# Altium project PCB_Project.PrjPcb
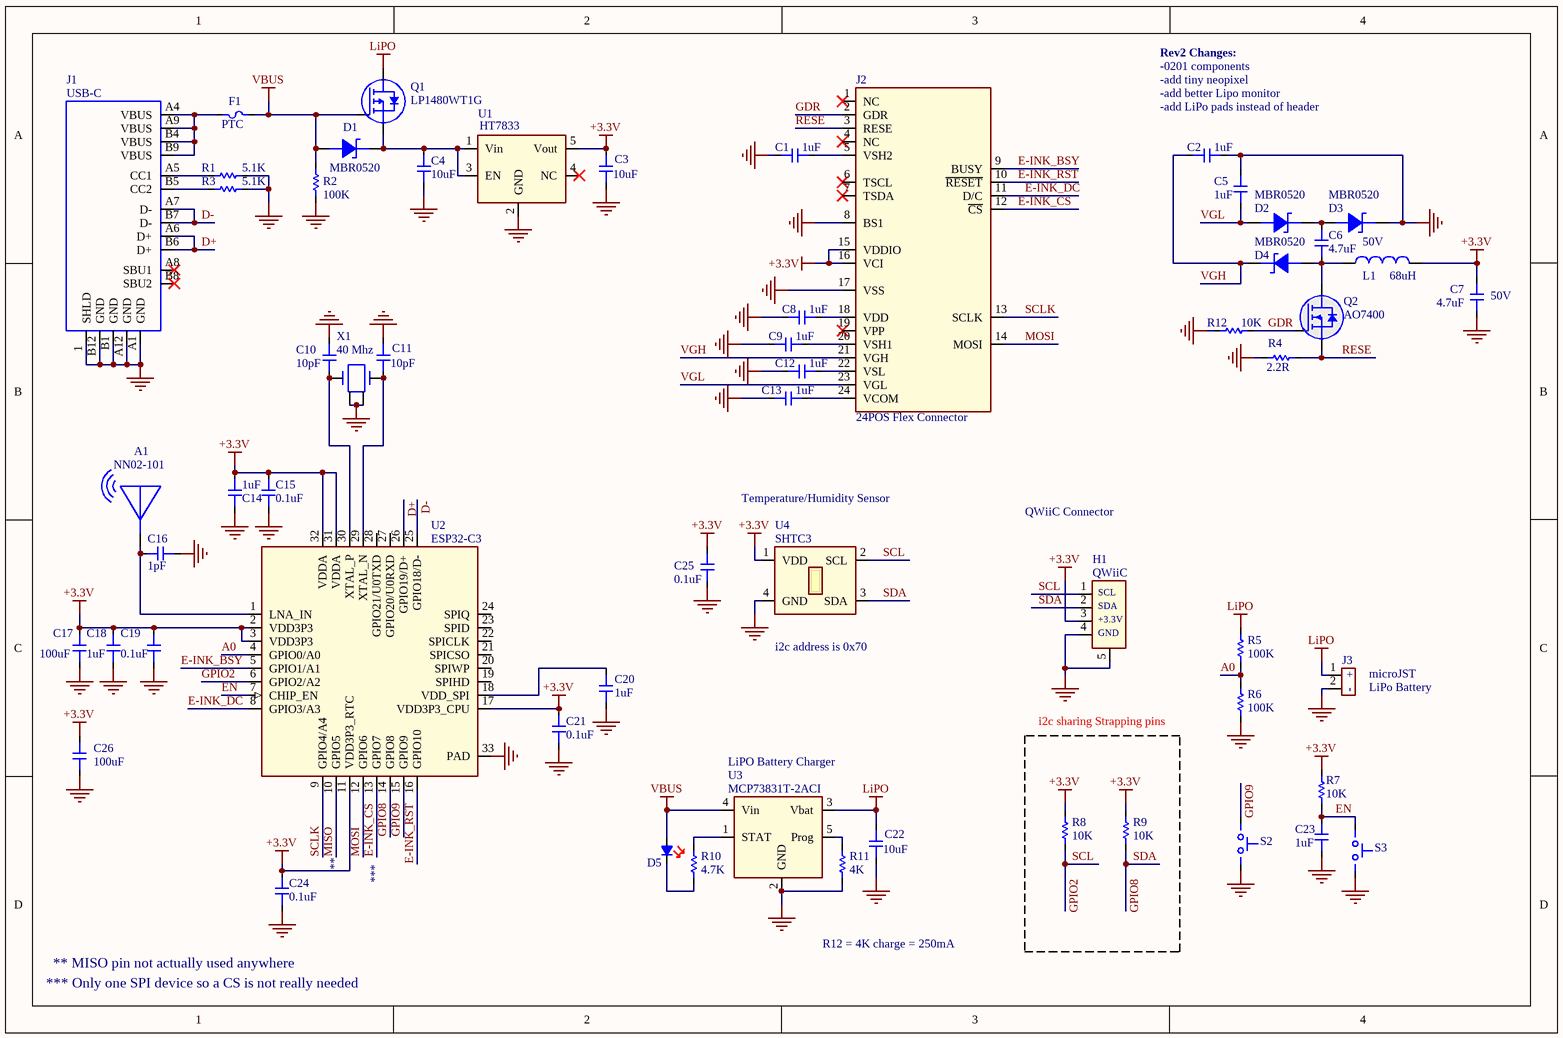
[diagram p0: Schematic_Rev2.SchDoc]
1 sheet, 59 parts. Net scope: global (net labels, ports and power ports of the same name join across sheets).
Board file: PCB_Rev2.PcbDoc

## Sheet Schematic_Rev2.SchDoc
size A4; SheetNumber: 1; SheetTotal: 1

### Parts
A1  NN02-101  [NN02-101]
C1  1uF  [CAPC0603X56N]
C2  1uF  [CAPC1005X56N]
C3  10uF  [CAPC2012X140N]
C4  10uF  [CAPC2012X140N]
C5  1uF  [CAPC1005X56N]
C6  4.7uF  [CAPC1608X09L]
C7  4.7uF  [CAPC1608X09L]
C8  1uF  [CAPC0603X56N]
C9  1uF  [CAPC0603X56N]
C10  10pF  [CAPC0603X56N]
C11  10pF  [CAPC0603X56N]
C12  1uF  [CAPC0603X56N]
C13  1uF  [CAPC0603X56N]
C14  1uF  [CAPC0603X56N]
C15  0.1uF  [CAPC0603X56N]
C16  1pF  [CAPC0603X56N]
C17  100uF  [CAPC3216X160N]
C18  1uF  [CAPC0603X56N]
C19  0.1uF  [CAPC0603X56N]
C20  1uF  [CAPC0603X56N]
C21  0.1uF  [CAPC0603X56N]
C22  10uF  [CAPC2012X140N]
C23  1uF  [CAPC0603X56N]
C24  0.1uF  [CAPC0603X56N]
C25  0.1uF  [CAPC0603X56N]
C26  100uF  [CAPC3216X160N]
D1  value MBR0520  [SOD123]  (hidden comment: MBR0520-TP)
D2  value MBR0520  [SOD123]  (hidden comment: MBR0520-TP)
D3  value MBR0520  [SOD123]  (hidden comment: MBR0520-TP)
D4  value MBR0520  [SOD123]  (hidden comment: MBR0520-TP)
D5  Red Led  [LED1005X40N-Red]  (value not drawn)
F1  PTC  [RESC1608X06L (0603 FOOTPRINT)]
H1  QWiiC  [SM04B-SRSS-TB]
J1  USB-C  [TYPE-C-31-M-12]
J2  24POS Flex Connector  [687124182122]
J3  CON2  [JST_Micro_2PIN]  (value not drawn)  (no BOM)
L1  68uH  [INDUCTOR, 3mmX3mm]
Q1  LP1480WT1G  [SC-70]
Q2  AO7400  [SC-70]
R1  5.1K  [RESC0603X40L (0201 footprint)]
R2  100K  [RESC0603X40L (0201 footprint)]
R3  5.1K  [RESC0603X40L (0201 footprint)]
R4  2.2R  [RESC0603X40L (0201 footprint)]
R5  100K  [RESC0603X40L (0201 footprint)]
R6  100K  [RESC0603X40L (0201 footprint)]
R7  10K  [RESC0603X40L (0201 footprint)]
R8  10K  [RESC0603X40L (0201 footprint)]
R9  10K  [RESC0603X40L (0201 footprint)]
R10  4.7K  [RESC0603X40L (0201 footprint)]
R11  4K  [RESC0603X40L (0201 footprint)]
R12  10K  [RESC0603X40L (0201 footprint)]
S2  (no value)  [TS-1088R-02526]
S3  (no value)  [TS-1088R-02526]
U1  HT7833  [SOT95P280X144-5N]
U2  ESP32-C3  [VFQFN-32 -ESP32-C3]
U3  value MCP73831T-2ACI  [SOT95P280X144-5N]  (hidden comment: MCP73831T-2ACI/OT)
U4  SHTC3  [DFN-4 (2.0mm X 2.0mm)]
X1  40 Mhz  [OSC20X16]

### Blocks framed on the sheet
i2c sharing Strapping pins: R8 R9

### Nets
+3.3V: C3.1 C7.1 C14.1 C15.1 C17.1 C18.2 C19.1 C21.1 C24.1 C25.1 C26.1 H1.3 J2.15(VDDIO) J2.16(VCI) L1.2 R7.1 R8.2 R9.2 U1.5(Vout) U2.2(VDD3P3) U2.3(VDD3P3) U2.11(VDD3P3_RTC) U2.17(VDD3P3_CPU) U2.31(VDDA) U2.32(VDDA) U4.1(VDD)
GND: C1.1 C2.2 C3.2 C4.2 C5.1 C7.2 C8.1 C9.1 C10.1 C11.1 C12.1 C13.1 C14.2 C15.2 C16.2 C17.2 C18.1 C19.2 C20.2 C21.2 C22.2 C23.2 C24.2 C25.2 C26.2 D3.1(Cathode) H1.4 H1.5 J1.1(SHLD) J1.A1(GND) J1.A12(GND) J1.B1(GND) J1.B12(GND) J2.8(BS1) J2.17(VSS) J3.2 R1.1 R2.2 R3.1 R4.2 R6.1 R11.1 R12.1 S2.2(B) S3.2(B) U1.2(GND) U2.33(PAD) U3.2(GND) U4.4(GND) X1.2 X1.4
LiPO: C22.1 J3.1 Q1.3(D) R5.2 U3.3(Vbat)
VBUS: D1.2(Annode) D5.2 F1.1 Q1.1(G) R2.1 U3.4(Vin)
A0: R5.1 R6.2 U2.4(GPIO0/A0)
D+: J1.A6(D+) J1.B6(D+) U2.26(GPIO19/D+)
D-: J1.A7(D-) J1.B7(D-) U2.25(GPIO18/D-)
E-INK_BSY: J2.9(BUSY) U2.5(GPIO1/A1)
E-INK_CS: J2.12(~{CS}) U2.13(GPIO7)
E-INK_DC: J2.11(D/C) U2.8(GPIO3/A3)
E-INK_RST: J2.10(~{RESET}) U2.16(GPIO10)
EN: C23.1 R7.2 S3.1(A) U2.7(CHIP_EN)
GDR: J2.2(GDR) Q2.1(G) R12.2
GPIO2: H1.1 R8.1 U2.6(GPIO2/A2) U4.2(SCL)  [also labelled SCL]
GPIO8: H1.2 R9.1 U2.14(GPIO8) U4.3(SDA)  [also labelled SDA]
GPIO9: S2.1(A) U2.15(GPIO9)
MISO: U2.10(GPIO5)
MOSI: J2.14(MOSI) U2.12(GPIO6)
RESE: J2.3(RESE) Q2.2(S) R4.1
SCLK: J2.13(SCLK) U2.9(GPIO4/A4)
VGH: C2.1 D4.1(Cathode) J2.21(VGH)
VGL: C5.2 D2.2(Annode) J2.23(VGL)
NetA1_1: A1.1 C16.1 U2.1(LNA_IN)
NetC1_2: C1.2 J2.5(VSH2)
NetC4_1: C4.1 D1.1(Cathode) Q1.2(S) U1.1(Vin) U1.3(EN)
NetC6_1: C6.1 D2.1(Cathode) D3.2(Annode)
NetC6_2: C6.2 D4.2(Annode) L1.1 Q2.3(D)
NetC8_2: C8.2 J2.18(VDD)
NetC9_2: C9.2 J2.20(VSH1)
NetC10_2: C10.2 U2.30(XTAL_P) X1.1
NetC11_2: C11.2 U2.29(XTAL_N) X1.3
NetC12_2: C12.2 J2.22(VSL)
NetC13_2: C13.2 J2.24(VCOM)
NetC20_1: C20.1 U2.18(VDD_SPI)
NetD5_1: D5.1 R10.1
NetF1_2: F1.2 J1.A4(VBUS) J1.A9(VBUS) J1.B4(VBUS) J1.B9(VBUS)
NetJ1_A5: J1.A5(CC1) R1.2
NetJ1_B5: J1.B5(CC2) R3.2
NetR10_2: R10.2 U3.1(STAT)
NetR11_2: R11.2 U3.5(Prog)

Not connected (* = marked no-connect by the designer): J1 A8(SBU1)* B8(SBU2)*; J2 1(NC)* 4(NC)* 6(TSCL)* 7(TSDA)* 19(VPP)*; U1 4(NC)*; U2 19(SPIHD) 20(SPIWP) 21(SPICSO) 22(SPICLK) 23(SPID) 24(SPIQ) 27(GPIO20/U0RXD) 28(GPIO21/U0TXD)

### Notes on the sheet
- Rev2 Changes:
- -0201 components
- -add tiny neopixel
- -add better Lipo monitor
- -add LiPo pads instead of header
- 50V
- (near C7) 50V
- Temperature/Humidity Sensor
- QWiiC Connector
- (near U4) i2c address is 0x70
- (near J3) LiPo Battery
- (near J3) microJST
- (near U3) LiPO Battery Charger
- (near C24) **
- ***
- *** Only one SPI device so a CS is not really needed
- (near C24) ** MISO pin not actually used anywhere
- R12 = 4K charge = 250mA

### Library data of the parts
A1 = NN02-101: Antenna Chip 2.4Gig; Manufacturer: Ignion; Vendor: Digi-Key; Value: Chip Antenna
C1 C8 C9 C12-C14 C18 C20 C23 = CAP_0201: CAP 1uF 0201; Part_Footprint: 0201
C2 C5 = CAP_0402: CAP 1uF 0402; Part_Footprint: 0402
C3 C4 C22 = CAP_0805: CAP 10uF 0805; Part_Footprint: 0805
C6 C7 = CAP_0603: CAP 4.7uF 50V 0603; Part_Footprint: 0603
C10 C11 = CAP_0201: CAP 10pF 0201; Part_Footprint: 0201
C15 C19 C21 C24 C25 = CAP_0201: CAP 0.1uF 0201; Part_Footprint: 0201
C16 = CAP_0201: CAP 1pF 0201; Part_Footprint: 0201
C17 C26 = CAP_1206: CAP 100uF 1206; Part_Footprint: 1206
D1-D4 = MBR0520-TP: DIODE SCHOTTKY 20V 500MA SOD-123; Manufacturer: Micro; Part_Number: C78746; Vendor: LCSC
D5 = LED_0402_SMALL_Red: LED Red 0402; Part_Number: C364556; Manufacturer: Lite-On; Part_Footprint: 0402; Vendor: LCSC
F1 = PTC_FUSE_0603: PTC FUSE 0.5mA hold, 1A trip 0603; Manufacturer: JDT Fuse; Part_Number: C2982257; Vendor: LCSC
H1 = SM04B-SRSS-TB: CONN HEADER 4POS .100 R/A QWIIC; Manufacturer: JST; Part_Number: PRT-14417; Vendor: Digi-Key
J1 = USB-C: CONN RECPT USB-C; Manufacturer: KHE; Part_Number: C165948; Part_Footprint: SMT; Vendor: LCSC
J2 = 687124182122: CONN FFC TOP/BOT 24POS 0.50MM R/A; Manufacturer: Wurth; Vendor: Digi-Key
J3 = JST_Micro_CONN_2PIN: JST MIcro CONN 2POS
L1 = 68uH: INDUCTOR 68uH 20% 4mmx4mm; Part_Number: C135265; Manufacturer: SXN; Vendor: LCSC
Q1 = LP1480WT1G: MOSFET P-CH 20V 1.4A SC-70; Manufacturer: LRC; Part_Number: C172434; Vendor: LCSC
Q2 = AO7400: MOSFET N-CH 20V 4A SC70-3; Manufacturer: VBSemi Elec; Vendor: LCSC
R1 R3 = RES_0201: RES 0201 5.1K; PartFootprint: 0201
R2 R5 R6 = RES_0201: RES 100K 0201; PartFootprint: 0201
R4 = RES_0201: RES 2.2R 0201; PartFootprint: 0201
R7-R9 R12 = RES_0201: RES 10K 0201; PartFootprint: 0201
R10 = RES_0201: RES 4.7K 0201; PartFootprint: 0201
R11 = RES_0201: RES 4K 0201; PartFootprint: 0201
S2 S3 = TS-1088R-02526: Tactile Micro Switch; Part_Number: C455281; Manufacturer: XUNPU; Part_Footprint: SMD; Vendor: LCSC
U1 = HT7833: IC LDO 3.3V 0.5A SOT23-5; Manufacturer: Holtek; Part_Number: C164106; Vendor: LCSC
U2 = ESP32-C3: WIFI/Bluetooth, VFQFN-32; Manufacturer: Espressif; Part_Number: C529594; Part_Footprint: QFN56; Vendor: LCSC
U3 = MCP73831T-2ACI/OT: Charger IC Lithium-Ion/Polymer SOT23-5; Manufacturer: Microchip; Vendor: Digi-Key
U4 = SHTC3: Humidity/Temperature Sensor; Manufacturer: Sensirion; Vendor: LCSC; Value: Temp/Humid
X1 = 40Mhz: CRYSTAL 40MHZ 10PF SMD; Part_Number: ECS-400-10-37B2-CKM; Manufacturer: ECS; Vendor: Digi-Key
